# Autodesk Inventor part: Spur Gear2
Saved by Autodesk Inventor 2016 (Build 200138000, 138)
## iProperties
Created: 2015-03
Part Number: Spur Gear2
Material: Steel
Document SubType Name: Modeling
Designer: Uglješa
Categories: <?xml version="1.0" encoding="UTF-16"?> <MemberInstance><Categories><FamilyTemplate><FamilyTemplateParameter ValueType="xs:double" Id="1" ObjectReferenceKey="da
Density: 7.85 g/cm^3
Appearance: Steel
Mass: 203.429 g
Surface Area: 109.446 cm^2
Volume: 25.9145 cm^3
CustomPartVersion: 1
Author: Uglješa
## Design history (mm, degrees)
sketch "Sketch1"
  geometry: C1 r 27.719 at (0, 0)
  constraints: 1 centre point
  dimensions: "d0" = 55.43862 diameter of C1 (= da_da)
extrude "Extrusion1" new body sketch "Sketch1" distance "d1" = 20 (= da_b); taper "d2" = 0 deg
workplane "Work Plane2"
sketch "Sketch2"
  geometry: C1 r 27.719 at (0, 0) reference; C2 r 25.143 at (0, 0)
  constraints: 1 centre point, 1 coincident
  dimensions: "d3" = 50.28571 diameter of C2 (= da_dw)
feature "Pitch Diameter" sketch "Sketch2" dims "d4" = 10, "d5" = 0
workplane "Work Plane8"
workplane "Work Plane9"
feature "Spur Gear" dims "da_b" = 20, "da_d" = 49.98646, "da_aw" = 80, "da_da" = 55.43862, "da_df" = 45.3343, "da_dw" = 50.28571, angle "da_beta" = 8 deg, "da_lefttooth" = 0, "da_righttooth" = 10
node "Keyway6"
body "Solid1"
body "Srf1"
feature "Hub Keyway"
other parameters: "d17" = 0, "d34" = 1.428 (computed from da_z), "d39" = 0, "d41" = 0, "d47" = 0, "d48" = 0
